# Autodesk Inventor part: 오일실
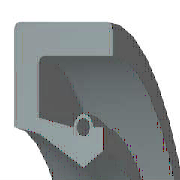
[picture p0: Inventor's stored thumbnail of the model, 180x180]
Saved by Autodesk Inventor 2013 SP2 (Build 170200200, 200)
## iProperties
IsCustomPart: 1
Created: 2015-12
Part Number: 오일실
Material: 고무
Description: 오일-실
Document SubType Name: Modeling
Standard: KS B 2804
Designer: mdu
Standards Organization: KS
Language: ko-KR
Size Designation: S - 15 30 7
Categories: <MemberInstance><Categories><Category DisplayName="샤프트 부품" InternalName="7f7aeb1f-a693-4053-b835-cee3144e0d98" Mnemonic="SHFT"><Category DisplayName="실링" Intern
Density: 0.93 g/cm^3
Author: mdu
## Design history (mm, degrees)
revolve "본체" stored, may be unused: angle "d17" = 90 deg
revolve "스프링1" stored, may be unused: angle "d18" = 90 deg
body "Solid1"
sketch "스케치1"
  geometry: L1 (0, 15)-(7, 15); L2 (7, 15)-(7, 13.75); L3 (7, 13.75)-(1.75, 13.75); L4 (0, 15)-(0, 9.6); L5 (0, 9.6)-(1.75, 9.25); L6 (1.75, 9.25)-(4.9, 7.5); L7 (4.9, 7.5)-(0, 7.5); L8 (6.3, 8.375)-(6.3, 9.6); L9 (0, 0)-(9.586, 0) reference; L10 (4.9, 7.5)-(6.3, 8.375); L11 (0, 18)-(0, -3) reference; L12 (-1.917, 0)-(11.503, 0) reference; L13 (4.2, 9.6)-(1.75, 10.09); L14 (1.75, 10.09)-(1.75, 13.75); L15 (6.3, 9.6)-(5.6, 9.6); C1 r 0.455 at (4.9, 9.6); A1 r 0.7 centre (4.9, 9.6) between (5.6, 9.6) and (4.2, 9.6)
  constraints: 26 end point, 5 horizontal alignment, 4 perpendicular, 2 centre point, 2 collinear, 2 horizontal, 2 parallel, 2 point on circle, 2 point on line, 2 vertical alignment, 1 coincident
  dimensions: "d0" = 30 diameter of L1 L9 (= SD2); "d1" = 16.75 diameter of L8.start L9 (= ABDM); "d2" = 1.25 distance of L1.end L2.end (computed from SD); "d3" = 0.91 diameter of C1 (= SPDI); "d4" = 1.4 diameter of A1 (= SPDA); "d5" = 15 diameter of L6.end L9 (= NND); "d6" = 18.5 diameter of L5.end L9 (= TKDM); "d7" = 19.2 diameter of L4.end L9 (= HLDM); "d8" = 4.9 distance from line of C1.centre L4 (= SPDST); "d9" = 6.3 distance between parallel lines of L8 L4 (= SDI); "d10" = 7 distance between parallel lines of L2 L4 (= SWDT); "d12" = 1.75 distance between parallel lines of L14 L4 (= SD)
fillet "모깎기1" dims "d11" = 0.3 (= RR)
other parameters: "SD2" = 30 [user parameter; used in 1 equation term], "SWDT" = 7 [user parameter; used in 1 equation term], "RR" = 0.3 [user parameter; used in 1 equation term], "SD" = 1.75 [user parameter; used in 2 equation terms], "NND" = 15 [user parameter; used in 1 equation term], "SPDA" = 1.4 [user parameter; used in 1 equation term], "SPDI" = 0.91 [user parameter; used in 1 equation term], "TKDM" = 18.5 [user parameter; used in 1 equation term], "HLDM" = 19.2 [user parameter; used in 1 equation term], "ABDM" = 16.75 [user parameter; used in 1 equation term], "SDI" = 6.3 [user parameter; used in 1 equation term], "SPDST" = 4.9 [user parameter; used in 1 equation term], "d13" = 0, "d14" = 0, "d15" = 0, "LAB" = 0.35 [user parameter]
